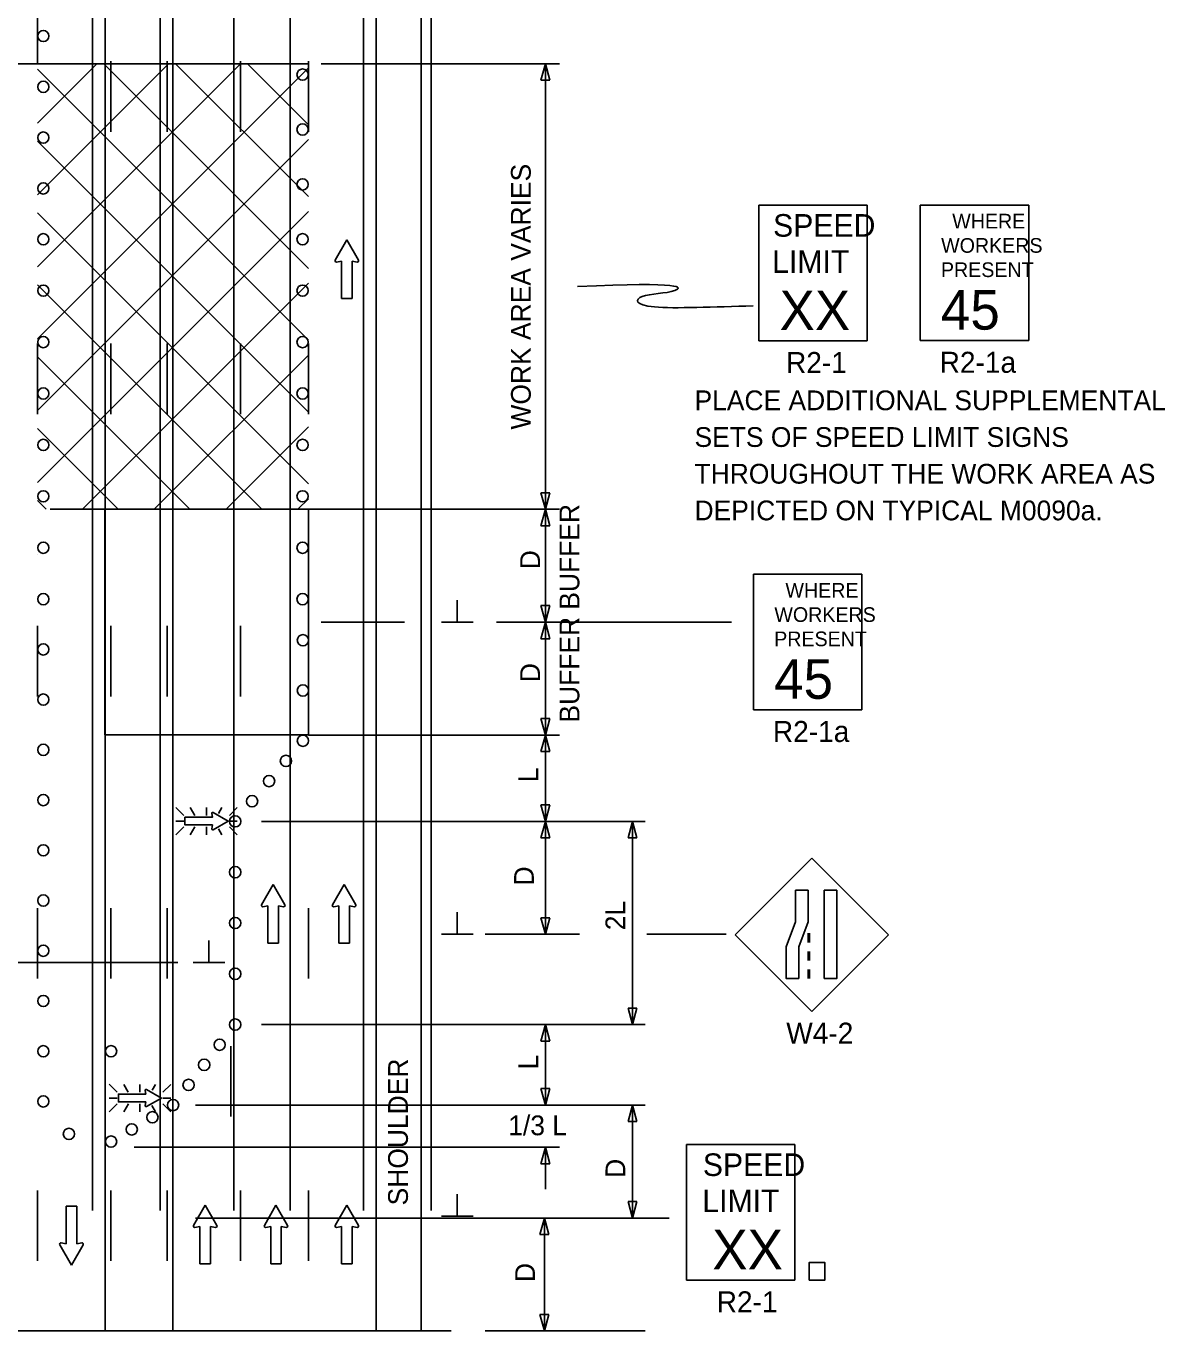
# Model space of a CAD drawing. Extents: x 16724 to 19504, y 5662 to 6979.
# Drawn here: x 16977.8 to 17381.3, y 6089 to 6551.3 of the extents above; entities that cross this region are included whole.
import ezdxf

# ---------------------------------------------------------------- set-up
doc = ezdxf.new("R2010")
doc.units = 0
for name, color, linetype in [('ALI_LEGAL_EX', 7, 'Continuous'), ('MT_SCRATCH_LEVEL_A', 7, 'Continuous'), ('MT_SCRATCH_LEVEL_E', 7, 'Continuous'), ('PAVT_EDGE_EX', 7, 'Continuous'), ('TRAFFIC_SIGNS_PR', 7, 'Continuous'), ('TYPICAL_TEXT_DIMEN_PR', 7, 'Continuous')]:
    doc.layers.add(name, color=color, linetype=linetype)

msp = doc.modelspace()

# ---------------------------------------------------------------- linework, layer by layer
at = {"layer": 'ALI_LEGAL_EX'}
for p, q in [((17001.36, 6131.68), (17001.36, 6928.96)), ((17001.36, 6131.68), (17001.36, 6928.96)), ((17025.36, 6131.68), (17025.36, 6928.96)), ((17025.36, 6131.68), (17025.36, 6928.96)), ((17051.36, 6131.68), (17051.36, 6928.96)), ((17051.36, 6131.68), (17051.36, 6928.96)), ((17071.36, 6131.68), (17071.36, 6928.96)), ((17071.36, 6131.68), (17071.36, 6928.96)), ((17097.36, 6131.68), (17097.36, 6928.96)), ((17097.36, 6131.68), (17097.36, 6928.96)), ((17121.36, 6131.68), (17121.36, 6928.96)), ((17121.36, 6131.68), (17121.36, 6928.96))]:
    msp.add_line(p, q, dxfattribs=at)
for points in [[(17007.81, 6513.81), (17007.81, 6538.81)], [(17027.81, 6513.81), (17027.81, 6538.81)], [(17053.81, 6513.81), (17053.81, 6538.81)], [(17077.81, 6513.81), (17077.81, 6538.81)], [(16981.81, 6413.81), (16981.81, 6438.81)], [(17007.81, 6413.81), (17007.81, 6438.81)], [(17027.81, 6413.81), (17027.81, 6438.81)], [(17053.81, 6413.81), (17053.81, 6438.81)], [(17077.81, 6413.81), (17077.81, 6438.81)], [(16981.81, 6313.81), (16981.81, 6338.81)], [(17007.81, 6313.81), (17007.81, 6338.81)], [(17027.81, 6313.81), (17027.81, 6338.81)], [(17053.81, 6313.81), (17053.81, 6338.81)], [(16981.81, 6213.81), (16981.81, 6238.81)], [(17007.81, 6213.81), (17007.81, 6238.81)], [(17027.81, 6213.81), (17027.81, 6238.81)], [(17077.81, 6213.81), (17077.81, 6238.81)], [(16981.81, 6113.81), (16981.81, 6138.81)], [(17007.81, 6113.81), (17007.81, 6138.81)], [(17027.81, 6113.81), (17027.81, 6138.81)], [(17053.81, 6113.81), (17053.81, 6138.81)], [(17077.81, 6113.81), (17077.81, 6138.81)]]:
    msp.add_lwpolyline(points, dxfattribs=at)
at = {"layer": 'MT_SCRATCH_LEVEL_A'}
for p, q in [((16981.81, 6537.94), (17077.81, 6537.94)), ((16981.81, 6465.98), (17053.77, 6537.94)), ((16981.81, 6491.44), (17028.32, 6537.94)), ((16981.81, 6516.89), (17002.86, 6537.94)), ((16981.81, 6440.53), (17077.81, 6536.53)), ((17077.81, 6465.44), (17005.31, 6537.94)), ((17077.81, 6490.9), (17030.77, 6537.94)), ((17077.81, 6516.35), (17056.22, 6537.94)), ((17077.81, 6439.99), (16981.81, 6535.99)), ((16981.81, 6415.07), (17077.81, 6511.07)), ((17077.81, 6414.53), (16981.81, 6510.53)), ((16981.81, 6389.61), (17077.81, 6485.61)), ((17077.81, 6389.07), (16981.81, 6485.07)), ((17061.33, 6380.1), (16981.81, 6459.62)), ((16997.75, 6380.1), (17077.81, 6460.16)), ((17023.21, 6380.1), (17077.81, 6434.7)), ((17035.87, 6380.1), (16981.81, 6434.16)), ((17010.42, 6380.1), (16981.81, 6408.71)), ((17048.66, 6380.1), (17077.81, 6409.25)), ((17074.12, 6380.1), (17077.81, 6383.79)), ((16984.96, 6380.1), (16981.81, 6383.25)), ((16986.31, 6380.1), (17082.31, 6380.1)), ((16981.81, 6364.16), (16981.81, 6364.16))]:
    msp.add_line(p, q, dxfattribs=at)
at = {"layer": 'MT_SCRATCH_LEVEL_E'}
for p, q in [((17091.43, 6475.59), (17087.32, 6468.35)), ((17091.43, 6475.59), (17087.32, 6468.35)), ((17095.57, 6468.35), (17091.43, 6475.59)), ((17095.57, 6468.35), (17091.43, 6475.59)), ((17087.8, 6467.67), (17089.58, 6467.99)), ((17087.8, 6467.67), (17089.58, 6467.99)), ((17089.58, 6467.99), (17089.58, 6454.73)), ((17089.58, 6467.99), (17089.58, 6454.73)), ((17093.32, 6454.73), (17093.32, 6467.99)), ((17093.32, 6467.99), (17095.1, 6467.67)), ((17093.32, 6454.73), (17093.32, 6467.99)), ((17093.32, 6467.99), (17095.1, 6467.67)), ((17089.58, 6454.73), (17093.32, 6454.73)), ((17089.58, 6454.73), (17093.32, 6454.73)), ((17065.37, 6247.22), (17061.26, 6239.98)), ((17065.37, 6247.22), (17061.26, 6239.98)), ((17069.51, 6239.98), (17065.37, 6247.22)), ((17069.51, 6239.98), (17065.37, 6247.22)), ((17090.46, 6247.22), (17086.35, 6239.98)), ((17090.46, 6247.22), (17086.35, 6239.98)), ((17094.6, 6239.98), (17090.46, 6247.22)), ((17094.6, 6239.98), (17090.46, 6247.22)), ((17061.74, 6239.29), (17063.51, 6239.61)), ((17061.74, 6239.29), (17063.51, 6239.61)), ((17063.51, 6239.61), (17063.51, 6226.35)), ((17063.51, 6239.61), (17063.51, 6226.35)), ((17067.26, 6226.35), (17067.26, 6239.61)), ((17067.26, 6239.61), (17069.03, 6239.29)), ((17067.26, 6226.35), (17067.26, 6239.61)), ((17067.26, 6239.61), (17069.03, 6239.29)), ((17086.83, 6239.29), (17088.6, 6239.61)), ((17086.83, 6239.29), (17088.6, 6239.61)), ((17088.6, 6239.61), (17088.6, 6226.35)), ((17088.6, 6239.61), (17088.6, 6226.35)), ((17092.35, 6226.35), (17092.35, 6239.61)), ((17092.35, 6239.61), (17094.12, 6239.29)), ((17092.35, 6226.35), (17092.35, 6239.61)), ((17092.35, 6239.61), (17094.12, 6239.29)), ((17063.51, 6226.35), (17067.26, 6226.35)), ((17063.51, 6226.35), (17067.26, 6226.35)), ((17088.6, 6226.35), (17092.35, 6226.35)), ((17088.6, 6226.35), (17092.35, 6226.35)), ((16995.74, 6133.16), (16991.99, 6133.16)), ((16991.99, 6133.16), (16991.99, 6119.9)), ((16995.74, 6133.16), (16991.99, 6133.16)), ((16991.99, 6133.16), (16991.99, 6119.9)), ((16995.74, 6119.9), (16995.74, 6133.16)), ((16995.74, 6119.9), (16995.74, 6133.16)), ((17041.25, 6133.62), (17037.14, 6126.38)), ((17041.25, 6133.62), (17037.14, 6126.38)), ((17045.4, 6126.38), (17041.25, 6133.62)), ((17045.4, 6126.38), (17041.25, 6133.62)), ((17066.34, 6133.62), (17062.23, 6126.38)), ((17066.34, 6133.62), (17062.23, 6126.38)), ((17070.48, 6126.38), (17066.34, 6133.62)), ((17070.48, 6126.38), (17066.34, 6133.62)), ((17091.43, 6133.62), (17087.32, 6126.38)), ((17091.43, 6133.62), (17087.32, 6126.38)), ((17095.57, 6126.38), (17091.43, 6133.62)), ((17095.57, 6126.38), (17091.43, 6133.62)), ((17037.62, 6125.69), (17039.4, 6126.01)), ((17037.62, 6125.69), (17039.4, 6126.01)), ((17039.4, 6126.01), (17039.4, 6112.75)), ((17039.4, 6126.01), (17039.4, 6112.75)), ((17043.14, 6112.75), (17043.14, 6126.01)), ((17043.14, 6126.01), (17044.92, 6125.69)), ((17043.14, 6112.75), (17043.14, 6126.01)), ((17043.14, 6126.01), (17044.92, 6125.69)), ((17062.71, 6125.69), (17064.49, 6126.01)), ((17062.71, 6125.69), (17064.49, 6126.01)), ((17064.49, 6126.01), (17064.49, 6112.75)), ((17064.49, 6126.01), (17064.49, 6112.75)), ((17068.23, 6112.75), (17068.23, 6126.01)), ((17068.23, 6126.01), (17070.01, 6125.69)), ((17068.23, 6112.75), (17068.23, 6126.01)), ((17068.23, 6126.01), (17070.01, 6125.69)), ((17087.8, 6125.69), (17089.58, 6126.01)), ((17087.8, 6125.69), (17089.58, 6126.01)), ((17089.58, 6126.01), (17089.58, 6112.75)), ((17089.58, 6126.01), (17089.58, 6112.75)), ((17093.32, 6112.75), (17093.32, 6126.01)), ((17093.32, 6126.01), (17095.1, 6125.69)), ((17093.32, 6112.75), (17093.32, 6126.01)), ((17093.32, 6126.01), (17095.1, 6125.69)), ((16991.99, 6119.9), (16990.22, 6120.22)), ((16991.99, 6119.9), (16990.22, 6120.22)), ((16997.51, 6120.22), (16995.74, 6119.9)), ((16997.51, 6120.22), (16995.74, 6119.9)), ((16989.74, 6119.53), (16993.89, 6112.29)), ((16989.74, 6119.53), (16993.89, 6112.29)), ((16993.89, 6112.29), (16998, 6119.53)), ((16993.89, 6112.29), (16998, 6119.53)), ((17039.4, 6112.75), (17043.14, 6112.75)), ((17039.4, 6112.75), (17043.14, 6112.75)), ((17064.49, 6112.75), (17068.23, 6112.75)), ((17064.49, 6112.75), (17068.23, 6112.75)), ((17089.58, 6112.75), (17093.32, 6112.75)), ((17089.58, 6112.75), (17093.32, 6112.75))]:
    msp.add_line(p, q, dxfattribs=at)
for centre, start, end in [((17087.72, 6468.13), 150.4248, 279.9638), ((17087.72, 6468.13), 150.4248, 279.9638), ((17095.16, 6468.13), 260.0362, 29.7731), ((17095.16, 6468.13), 260.0362, 29.7731), ((17061.66, 6239.75), 150.4248, 279.9638), ((17061.66, 6239.75), 150.4248, 279.9638), ((17069.1, 6239.75), 260.0362, 29.7731), ((17069.1, 6239.75), 260.0362, 29.7731), ((17086.75, 6239.75), 150.4248, 279.9638), ((17086.75, 6239.75), 150.4248, 279.9638), ((17094.19, 6239.75), 260.0362, 29.7731), ((17094.19, 6239.75), 260.0362, 29.7731), ((17037.54, 6126.15), 150.4248, 279.9638), ((17037.54, 6126.15), 150.4248, 279.9638), ((17044.99, 6126.15), 260.0362, 29.7731), ((17044.99, 6126.15), 260.0362, 29.7731), ((17062.63, 6126.15), 150.4248, 279.9638), ((17062.63, 6126.15), 150.4248, 279.9638), ((17070.07, 6126.15), 260.0362, 29.7731), ((17070.07, 6126.15), 260.0362, 29.7731), ((17087.72, 6126.15), 150.4248, 279.9638), ((17087.72, 6126.15), 150.4248, 279.9638), ((17095.16, 6126.15), 260.0362, 29.7731), ((17095.16, 6126.15), 260.0362, 29.7731), ((16990.15, 6119.76), 80.0362, 209.7731), ((16990.15, 6119.76), 80.0362, 209.7731), ((16997.59, 6119.76), 330.4248, 99.9638), ((16997.59, 6119.76), 330.4248, 99.9638)]:
    msp.add_arc(centre, 0.463, start, end, dxfattribs=at)
at = {"layer": 'PAVT_EDGE_EX'}
for p, q in [((17005.81, 6917), (17005.81, 6089.02)), ((17029.81, 6917), (17029.81, 6089.02)), ((17101.81, 6917), (17101.81, 6089.02)), ((17117.81, 6917), (17117.81, 6089.02))]:
    msp.add_line(p, q, dxfattribs=at)
for points in [[(17029.81, 6617.94), (16981.81, 6617.94), (16981.81, 6537.94), (17029.81, 6537.94)], [(17077.81, 6380.1), (17005.75, 6380.1), (17005.75, 6300.19), (17077.81, 6300.19)]]:
    msp.add_lwpolyline(points, close=True, dxfattribs=at)
for points in [[(17025.36, 6164.93), (17025.36, 6189.93)], [(17050.36, 6164.93), (17050.36, 6189.93)]]:
    msp.add_lwpolyline(points, dxfattribs=at)
at = {"layer": 'TRAFFIC_SIGNS_PR'}
for p, q in [((17237.45, 6487.8), (17275.85, 6487.8)), ((17237.45, 6439.8), (17237.45, 6487.8)), ((17275.85, 6439.8), (17275.85, 6487.8)), ((17294.65, 6487.89), (17333.05, 6487.89)), ((17294.65, 6439.89), (17294.65, 6487.89)), ((17333.05, 6439.89), (17333.05, 6487.89)), ((17237.45, 6439.8), (17275.85, 6439.8)), ((17294.65, 6439.89), (17333.05, 6439.89)), ((17235.55, 6357.1), (17273.95, 6357.1)), ((17235.55, 6309.1), (17235.55, 6357.1)), ((17273.95, 6309.1), (17273.95, 6357.1)), ((17235.55, 6309.1), (17273.95, 6309.1)), ((17033.66, 6271.64), (17030.84, 6274.46)), ((17035.96, 6274.46), (17037.58, 6271.64)), ((17041.74, 6271.64), (17041.74, 6274.46)), ((17047.21, 6274.46), (17046.01, 6272.36)), ((17052.65, 6274.46), (17049.83, 6271.64)), ((17033.66, 6269.61), (17030.84, 6269.61)), ((17049.83, 6269.61), (17052.65, 6269.61)), ((17033.66, 6267.57), (17030.84, 6264.75)), ((17037.61, 6267.57), (17035.98, 6264.75)), ((17041.74, 6267.57), (17041.74, 6264.75)), ((17045.93, 6266.94), (17047.19, 6264.75)), ((17052.65, 6264.76), (17049.83, 6267.57)), ((17256.19, 6256.53), (17229.04, 6229.38)), ((17283.35, 6229.38), (17256.19, 6256.53)), ((17229.04, 6229.38), (17256.19, 6202.23)), ((17254.95, 6229.87), (17254.95, 6226.67)), ((17255.35, 6229.87), (17255.35, 6226.67)), ((17256.19, 6202.23), (17283.35, 6229.38)), ((17254.95, 6223.47), (17254.95, 6220.27)), ((17255.35, 6223.47), (17255.35, 6220.27)), ((17254.95, 6217.07), (17254.95, 6213.87)), ((17255.35, 6217.07), (17255.35, 6213.87)), ((17010.08, 6173.55), (17007.26, 6176.38)), ((17012.38, 6176.37), (17014, 6173.55)), ((17018.16, 6173.55), (17018.16, 6176.37)), ((17023.63, 6176.37), (17022.43, 6174.28)), ((17029.07, 6176.37), (17026.25, 6173.55)), ((17010.08, 6171.52), (17007.26, 6171.52)), ((17026.25, 6171.52), (17029.07, 6171.52)), ((17010.08, 6169.49), (17007.26, 6166.67)), ((17014.03, 6169.49), (17012.4, 6166.67)), ((17018.16, 6169.49), (17018.16, 6166.67)), ((17022.35, 6168.86), (17023.61, 6166.67)), ((17029.07, 6166.67), (17026.25, 6169.49)), ((17211.82, 6155.04), (17250.22, 6155.04)), ((17211.82, 6107.04), (17211.82, 6155.04)), ((17250.22, 6107.04), (17250.22, 6155.04)), ((17211.82, 6107.04), (17250.22, 6107.04))]:
    msp.add_line(p, q, dxfattribs=at)
for points in [[(17043.57, 6272.29), (17043.8, 6270.99), (17034.08, 6270.99), (17034.08, 6268.25), (17043.8, 6268.25), (17043.57, 6266.94)], [(17044.07, 6266.59), (17049.38, 6269.61), (17044.07, 6272.65)], [(17019.99, 6174.2), (17020.22, 6172.91), (17010.5, 6172.91), (17010.5, 6170.16), (17020.22, 6170.16), (17019.99, 6168.86)], [(17020.49, 6168.51), (17025.8, 6171.52), (17020.49, 6174.56)]]:
    msp.add_lwpolyline(points, dxfattribs=at)
for points in [[(17254.95, 6245.11), (17254.95, 6233.93), (17251.6, 6225.05), (17251.6, 6213.87), (17247.11, 6213.87), (17247.11, 6225.05), (17250.45, 6233.93), (17250.45, 6245.11)], [(17265.08, 6245.11), (17265.08, 6213.87), (17260.59, 6213.87), (17260.59, 6245.11)], [(17255.24, 6107.04), (17260.83, 6107.04), (17260.83, 6113.21), (17255.24, 6113.21)]]:
    msp.add_lwpolyline(points, close=True, dxfattribs=at)
for centre in [(16983.91, 6547.76), (16983.91, 6529.76), (17075.79, 6534.08), (16983.91, 6511.76), (17075.79, 6514.64), (16983.91, 6493.76), (17075.79, 6495.2), (16983.91, 6475.76), (17075.79, 6475.76), (17075.79, 6475.76), (17075.79, 6475.76), (16983.91, 6457.55), (17075.79, 6457.55), (16983.91, 6439.33), (17075.79, 6439.33), (16983.91, 6421.12), (17075.79, 6421.12), (16983.91, 6402.9), (17075.79, 6402.9), (16983.91, 6384.69), (17075.79, 6384.69), (16983.91, 6366.48), (17075.79, 6366.48), (16983.91, 6348.26), (16983.91, 6348.26), (17075.79, 6348.26), (17075.88, 6333.69), (16983.91, 6330.47), (16983.91, 6312.67), (17075.88, 6315.89), (16983.91, 6294.87), (17075.88, 6298.1), (17069.88, 6290.96), (17063.88, 6283.82), (16983.91, 6277.08), (17057.88, 6276.68), (17051.88, 6269.54), (16983.91, 6259.28), (17051.88, 6251.53), (16983.91, 6241.49), (17051.88, 6233.53), (16983.91, 6223.69), (17051.88, 6215.53), (16983.91, 6205.9), (17051.88, 6197.53), (16983.91, 6188.1), (17007.91, 6188.1), (17046.39, 6190.4), (17040.89, 6183.28), (17035.39, 6176.15), (16983.91, 6170.31), (17022.57, 6164.72), (17029.9, 6169.02), (17015.24, 6160.41), (16992.97, 6158.81), (17007.91, 6156.1)]:
    msp.add_circle(centre, 2, dxfattribs=at)
for centre, start, end in [((17043.91, 6272.35), 61.4833, 189.9593), ((17043.91, 6266.89), 170.7308, 298.8916), ((17020.33, 6174.26), 61.4833, 189.9593), ((17020.33, 6168.81), 170.7308, 298.8916)]:
    msp.add_arc(centre, 0.341, start, end, dxfattribs=at)
at = {"layer": 'TYPICAL_TEXT_DIMEN_PR'}
for p, q in [((16868.81, 6537.94), (16981.81, 6537.94)), ((17166.81, 6537.94), (17082.31, 6537.94)), ((17160.24, 6532.08), (17161.81, 6537.94)), ((17161.81, 6380.1), (17161.81, 6537.94)), ((17161.81, 6537.94), (17163.38, 6532.08)), ((17161.81, 6532.08), (17160.24, 6532.08)), ((17163.38, 6532.08), (17161.81, 6532.08)), ((17161.81, 6380.1), (17160.24, 6385.96)), ((17160.24, 6385.96), (17161.81, 6385.96)), ((17161.81, 6385.96), (17163.38, 6385.96)), ((17163.38, 6385.96), (17161.81, 6380.1)), ((17166.81, 6380.1), (17082.31, 6380.1)), ((17160.24, 6374.24), (17161.81, 6380.1)), ((17161.81, 6380.1), (17163.38, 6374.24)), ((17161.81, 6380.1), (17161.81, 6340.1)), ((17161.81, 6374.24), (17160.24, 6374.24)), ((17163.38, 6374.24), (17161.81, 6374.24)), ((17130.57, 6340.1), (17130.57, 6347.88)), ((17161.81, 6340.1), (17160.24, 6345.96)), ((17160.24, 6345.96), (17161.81, 6345.96)), ((17161.81, 6345.96), (17163.38, 6345.96)), ((17163.38, 6345.96), (17161.81, 6340.1)), ((17111.84, 6340.1), (17082.31, 6340.1)), ((17136.19, 6340.1), (17124.94, 6340.1)), ((17227.74, 6340.1), (17144.5, 6340.1)), ((17160.24, 6334.24), (17161.81, 6340.1)), ((17161.81, 6340.1), (17163.38, 6334.24)), ((17161.81, 6340.1), (17161.81, 6300.1)), ((17161.81, 6334.24), (17160.24, 6334.24)), ((17163.38, 6334.24), (17161.81, 6334.24)), ((17161.81, 6300.1), (17160.24, 6305.96)), ((17160.24, 6305.96), (17161.81, 6305.96)), ((17161.81, 6305.96), (17163.38, 6305.96)), ((17163.38, 6305.96), (17161.81, 6300.1)), ((17166.81, 6300.1), (17077.81, 6300.1)), ((17160.24, 6294.24), (17161.81, 6300.1)), ((17161.81, 6300.1), (17163.38, 6294.24)), ((17161.81, 6269.52), (17161.81, 6300.1)), ((17161.81, 6294.24), (17160.24, 6294.24)), ((17163.38, 6294.24), (17161.81, 6294.24)), ((17161.81, 6269.52), (17160.24, 6275.39)), ((17160.24, 6275.39), (17161.81, 6275.39)), ((17161.81, 6275.39), (17163.38, 6275.39)), ((17163.38, 6275.39), (17161.81, 6269.52)), ((17197.18, 6269.52), (17061.17, 6269.52)), ((17160.24, 6263.66), (17161.81, 6269.52)), ((17161.81, 6269.52), (17161.81, 6229.52)), ((17161.81, 6269.52), (17163.38, 6263.66)), ((17191.09, 6263.66), (17192.66, 6269.52)), ((17192.66, 6269.52), (17192.66, 6197.53)), ((17192.66, 6269.52), (17194.23, 6263.66)), ((17161.81, 6263.66), (17160.24, 6263.66)), ((17163.38, 6263.66), (17161.81, 6263.66)), ((17192.66, 6263.66), (17191.09, 6263.66)), ((17194.23, 6263.66), (17192.66, 6263.66)), ((17130.57, 6229.52), (17130.57, 6237.31)), ((17161.81, 6229.52), (17160.24, 6235.39)), ((17160.24, 6235.39), (17161.81, 6235.39)), ((17161.81, 6235.39), (17163.38, 6235.39)), ((17163.38, 6235.39), (17161.81, 6229.52)), ((17042.61, 6219.52), (17042.61, 6227.31)), ((17136.19, 6229.52), (17124.94, 6229.52)), ((17173.9, 6229.52), (17140.44, 6229.52)), ((17197.71, 6229.52), (17225.85, 6229.52)), ((17031.52, 6219.52), (16855.81, 6219.52)), ((17048.23, 6219.52), (17036.98, 6219.52)), ((17192.66, 6197.53), (17191.09, 6203.4)), ((17191.09, 6203.4), (17192.66, 6203.4)), ((17192.66, 6203.4), (17194.23, 6203.4)), ((17194.23, 6203.4), (17192.66, 6197.53)), ((17197.18, 6197.53), (17061.17, 6197.53)), ((17160.24, 6191.67), (17161.81, 6197.53)), ((17161.81, 6169.02), (17161.81, 6197.53)), ((17161.81, 6197.53), (17163.38, 6191.67)), ((17161.81, 6191.67), (17160.24, 6191.67)), ((17163.38, 6191.67), (17161.81, 6191.67)), ((17161.81, 6169.02), (17160.24, 6174.89)), ((17160.24, 6174.89), (17161.81, 6174.89)), ((17161.81, 6174.89), (17163.38, 6174.89)), ((17163.38, 6174.89), (17161.81, 6169.02)), ((17197.18, 6169.02), (17037.77, 6169.02)), ((17191.09, 6163.16), (17192.66, 6169.02)), ((17192.66, 6169.02), (17194.23, 6163.16)), ((17192.66, 6169.02), (17192.66, 6129.02)), ((17192.66, 6163.16), (17191.09, 6163.16)), ((17194.23, 6163.16), (17192.66, 6163.16)), ((17166.81, 6154.1), (17016.04, 6154.1)), ((17161.81, 6154.1), (17160.24, 6148.24)), ((17161.81, 6154.1), (17161.81, 6139.18)), ((17163.38, 6148.24), (17161.81, 6154.1)), ((17160.24, 6148.24), (17161.81, 6148.24)), ((17161.81, 6148.24), (17163.38, 6148.24)), ((17130.57, 6129.67), (17130.57, 6137.46)), ((17192.66, 6129.02), (17191.09, 6134.89)), ((17191.09, 6134.89), (17192.66, 6134.89)), ((17192.66, 6134.89), (17194.23, 6134.89)), ((17194.23, 6134.89), (17192.66, 6129.02)), ((17136.19, 6129.67), (17124.94, 6129.67)), ((17205.66, 6129.02), (17037.77, 6129.02)), ((17159.87, 6123.16), (17161.44, 6129.02)), ((17161.44, 6129.02), (17161.44, 6089.02)), ((17161.44, 6129.02), (17163.01, 6123.16)), ((17161.44, 6123.16), (17159.87, 6123.16)), ((17163.01, 6123.16), (17161.44, 6123.16)), ((17161.44, 6089.02), (17159.87, 6094.89)), ((17159.87, 6094.89), (17161.44, 6094.89)), ((17161.44, 6094.89), (17163.01, 6094.89)), ((17163.01, 6094.89), (17161.44, 6089.02)), ((16915.6, 6089.02), (17128.47, 6089.02)), ((17140.44, 6089.02), (17197.18, 6089.02))]:
    msp.add_line(p, q, dxfattribs=at)
msp.add_open_spline([(17173.2, 6459.02), (17211.3, 6460.79), (17210.1, 6456.51), (17193.36, 6456.51), (17193.36, 6450.4), (17221.64, 6451.84), (17235.48, 6452.13)], degree=3, dxfattribs=at)

# ---------------------------------------------------------------- texts
at = {"layer": 'TRAFFIC_SIGNS_PR'}
for s, height, p in [('SPEED', 8, (17242.48, 6476.66)), ('WHERE', 5.2, (17305.96, 6479.57)), ('WORKERS', 5.2, (17302.03, 6470.97)), ('LIMIT', 8, (17242.15, 6463.86)), ('PRESENT', 5.2, (17301.96, 6462.37)), ('45', 14.031, (17301.95, 6443.74)), ('XX', 14.031, (17244.76, 6443.56)), ('R2-1', 7.44, (17247.06, 6428.36)), ('R2-1a', 7.44, (17301.5, 6428.45)), ('PLACE ADDITIONAL SUPPLEMENTAL', 7, (17214.65, 6415.19)), ('SETS OF SPEED LIMIT SIGNS', 7, (17214.65, 6402.19)), ('THROUGHOUT THE WORK AREA AS', 7, (17214.65, 6389.19)), ('DEPICTED ON TYPICAL M0090a.', 7, (17214.65, 6376.19)), ('WHERE', 5.2, (17246.86, 6348.79)), ('WORKERS', 5.2, (17242.94, 6340.19)), ('PRESENT', 5.2, (17242.87, 6331.59)), ('45', 14.031, (17242.86, 6312.96)), ('R2-1a', 7.44, (17242.41, 6297.66)), ('W4-2', 7.44, (17247.15, 6190.79)), ('SPEED', 8, (17217.59, 6143.9)), ('LIMIT', 8, (17217.42, 6131.1)), ('XX', 14.031, (17220.93, 6110.8)), ('R2-1', 7.44, (17222.5, 6095.6))]:
    msp.add_text(s, height=height, dxfattribs=at).set_placement(p)
at = {"layer": 'TYPICAL_TEXT_DIMEN_PR'}
for s, p in [('WORK AREA VARIES', (17156.62, 6408.34)), ('BUFFER', (17173.84, 6344.53)), ('D', (17159.89, 6358.85)), ('BUFFER', (17173.84, 6304.53)), ('D', (17159.89, 6318.85)), ('L', (17159.25, 6283.39)), ('D', (17157.71, 6246.82)), ('2L', (17190.1, 6230.97)), ('SHOULDER', (17113.09, 6133.49)), ('L', (17159.25, 6181.67)), ('D', (17190.1, 6143.24)), ('D', (17158.11, 6106.32))]:
    msp.add_text(s, height=7, rotation=90, dxfattribs=at).set_placement(p)
msp.add_text('1/3 L', height=7, dxfattribs=at).set_placement((17148.65, 6158.34))

doc.saveas('drawing.dxf')
